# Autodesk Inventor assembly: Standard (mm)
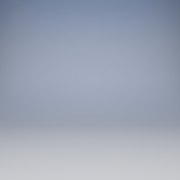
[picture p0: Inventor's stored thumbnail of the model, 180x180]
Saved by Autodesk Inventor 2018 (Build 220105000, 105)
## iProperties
Created: 2017-02
Part Number: Standard (mm)
Material: Ogólny
Document SubType Name: Assembly
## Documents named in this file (1)
- C:\Users\Joffi\Desktop\Templates.Base\Metric.Base\Standard (mm).iam
